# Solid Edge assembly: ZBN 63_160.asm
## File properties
Title: Zylinder
Author: bmolnar
Template: iso metric assembly.asm
Last saved by: bmolnar
Revision: 28
Application: Solid Edge
Username: bmolnar
Dokumentum tartalom típus: 1
Document Number: ZBN 63/160
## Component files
Profilrohr.par
Kolbenstange.par
Kit_2.par
Kit_1.par
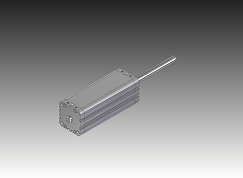
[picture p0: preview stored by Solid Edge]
